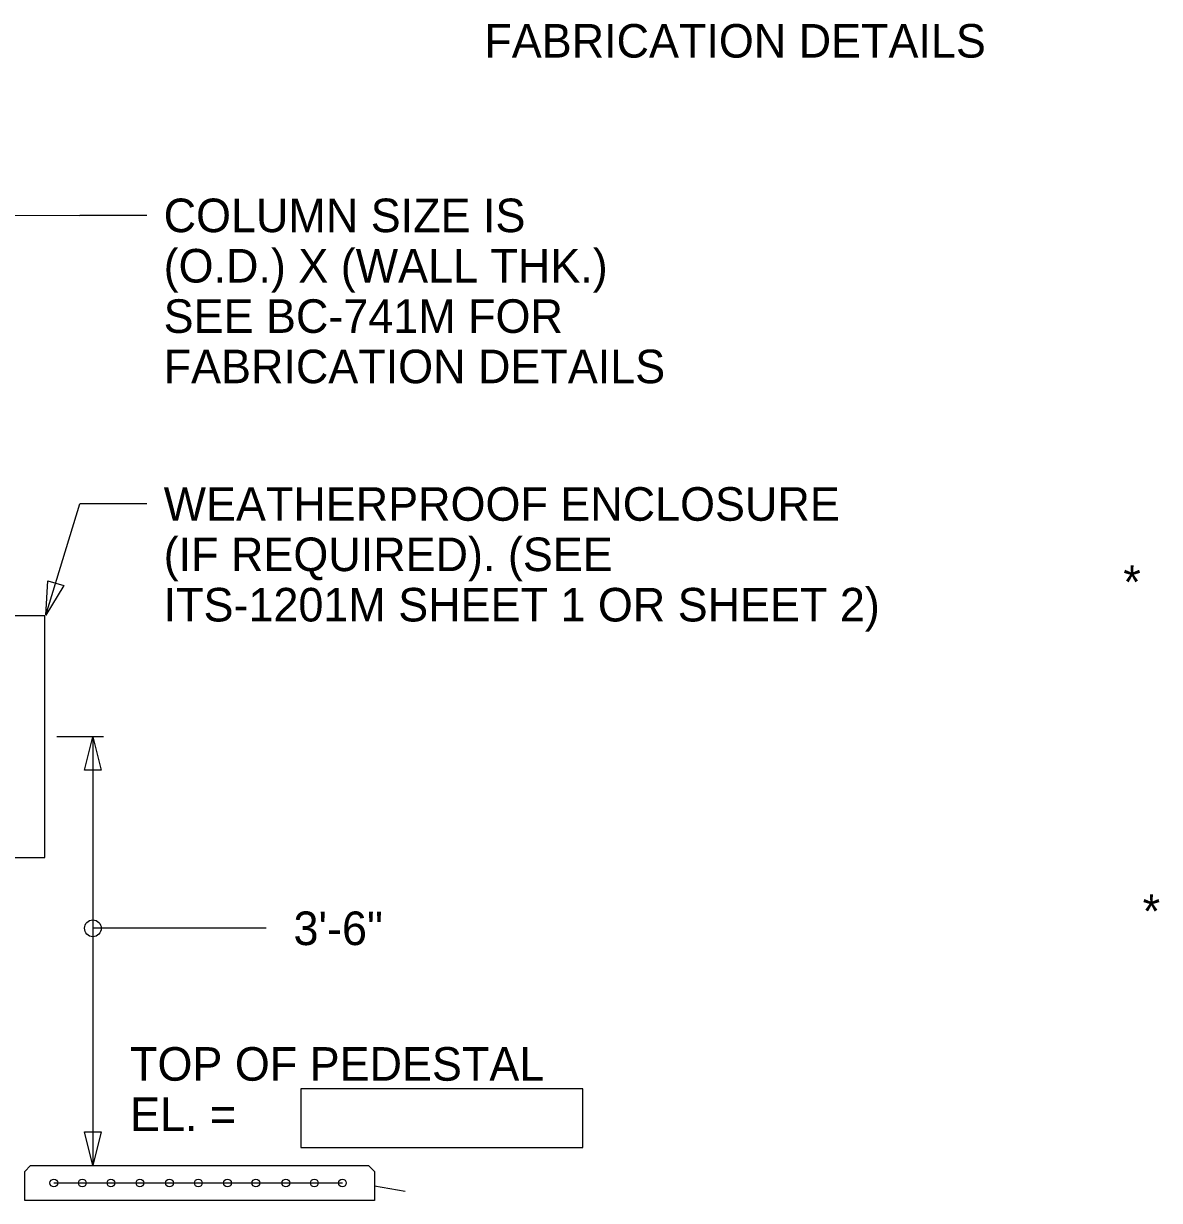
# Model space of a CAD drawing. Extents: x 3829340 to 3831660, y 499389 to 501171.
# Drawn here: x 3829574 to 3829675.5, y 499699.3 to 499804.5 of the extents above; entities that cross this region are included whole.
import ezdxf

# ---------------------------------------------------------------- set-up
doc = ezdxf.new("R2010")
doc.units = 0
for name, color, linetype in [('0-conc', 7, 'Continuous'), ('0-DEVICE ATTACH', 7, 'Continuous'), ('3', 7, 'Continuous'), ('BASELINES', 7, 'Continuous'), ('DIM TXT', 7, 'Continuous'), ('grade', 7, 'Continuous')]:
    doc.layers.add(name, color=color, linetype=linetype)

msp = doc.modelspace()

# ---------------------------------------------------------------- linework, layer by layer
at = {"layer": '0-conc'}
for p, q in [((3829574.08, 499701.94), (3829574.6, 499702.46)), ((3829574.08, 499699.34), (3829574.08, 499701.94)), ((3829574.6, 499702.46), (3829604.8, 499702.46)), ((3829604.8, 499702.46), (3829605.32, 499701.94)), ((3829605.32, 499701.94), (3829605.32, 499699.34)), ((3829605.32, 499699.34), (3829574.08, 499699.34))]:
    msp.add_line(p, q, dxfattribs=at)
at = {"layer": '0-DEVICE ATTACH'}
msp.add_lwpolyline([(3829569.11, 499729.98), (3829575.88, 499729.98), (3829575.88, 499751.59), (3829569.11, 499751.59)], close=True, dxfattribs=at)
msp.add_lwpolyline([(3829569.11, 499729.98), (3829575.88, 499729.98), (3829575.88, 499751.59), (3829569.11, 499751.59)], close=True, dxfattribs=at)
msp.add_lwpolyline([(3829569.11, 499729.98), (3829575.88, 499729.98), (3829575.88, 499751.59), (3829569.11, 499751.59)], close=True, dxfattribs=at)
at = {"layer": 'BASELINES'}
msp.add_line((3829576.68, 499700.9), (3829602.46, 499700.9), dxfattribs=at)
for centre in [(3829576.68, 499700.9), (3829579.22, 499700.9), (3829581.78, 499700.9), (3829584.37, 499700.9), (3829587.01, 499700.9), (3829589.59, 499700.9), (3829592.19, 499700.9), (3829594.73, 499700.9), (3829597.41, 499700.9), (3829599.95, 499700.9), (3829602.46, 499700.9)]:
    msp.add_circle(centre, 0.345, dxfattribs=at)
at = {"layer": 'DIM TXT'}
for p, q in [((3829566.5, 499787.38), (3829578.99, 499787.37)), ((3829584.99, 499787.37), (3829578.99, 499787.37)), ((3829575.96, 499751.64), (3829578.99, 499761.58)), ((3829584.99, 499761.58), (3829578.99, 499761.58)), ((3829581.13, 499740.78), (3829576.96, 499740.78)), ((3829580.17, 499740.78), (3829580.17, 499702.46)), ((3829589.64, 499723.66), (3829580.17, 499723.66)), ((3829595.64, 499723.66), (3829589.64, 499723.66))]:
    msp.add_line(p, q, dxfattribs=at)
for points in [[(3829577.56, 499754.28), (3829575.96, 499751.64), (3829576.13, 499754.72)], [(3829579.42, 499737.78), (3829580.17, 499740.78), (3829580.92, 499737.78)], [(3829598.75, 499704.06), (3829623.94, 499704.06), (3829623.94, 499709.31), (3829598.75, 499709.31)], [(3829580.92, 499705.46), (3829580.17, 499702.46), (3829579.42, 499705.46)]]:
    msp.add_lwpolyline(points, close=True, dxfattribs=at)
msp.add_circle((3829580.17, 499723.66), 0.75, dxfattribs=at)
at = {"layer": 'grade'}
msp.add_line((3829605.32, 499700.64), (3829608.08, 499700.17), dxfattribs=at)

# ---------------------------------------------------------------- texts
at = {"layer": '3'}
for p in [(3829672.22, 499753.11), (3829673.95, 499723.69)]:
    msp.add_text('*', height=3, dxfattribs=at).set_placement(p)
at = {"layer": 'DIM TXT'}
for s, height, p in [('FABRICATION DETAILS', 2.9999, (3829615.14, 499801.47)), ('COLUMN SIZE IS', 2.9999, (3829586.49, 499785.87)), ('(O.D.) X (WALL THK.)', 2.9999, (3829586.49, 499781.37)), ('SEE BC-741M FOR', 2.9999, (3829586.49, 499776.87)), ('FABRICATION DETAILS', 2.9999, (3829586.49, 499772.37)), ('WEATHERPROOF ENCLOSURE', 2.9999, (3829586.49, 499760.08)), ('(IF REQUIRED). (SEE', 2.9999, (3829586.49, 499755.58)), ('ITS-1201M SHEET 1 OR SHEET 2)', 2.9999, (3829586.49, 499751.08)), ('3\'-6"', 3, (3829598.09, 499722.16)), ('TOP OF PEDESTAL', 2.9999, (3829583.49, 499710.04)), ('EL. =', 3, (3829583.49, 499705.54))]:
    msp.add_text(s, height=height, dxfattribs=at).set_placement(p)

doc.saveas('drawing.dxf')
